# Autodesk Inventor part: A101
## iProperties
Shininess: 64.0
Length Units: 11272
Angle Units: 11279
Time Units: 11290
Mass Units: 11286
Length Display Precision: 3
Compacted: True
Part Number: A101
Document SubType Name: Modeling
Created: 2002-11
Designer: E. MOSS
Project: EVC
Description: C-BRACKET
Authority: MS. TEACHER
Density: 0.0
Volumn: 0.0
Area: 0.0
PropertySet Name: Model Information
Control State: 0
Master: False
Checked Out: False
Author: E. MOSS
Revision Number: A
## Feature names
1. Extrusion1
2. Extrusion2
3. Extrusion3
4. Extrusion4
5. Extrusion5
6. Mirror1
7. Fillet1
8. Hole1
9. texture [Extrusion]
